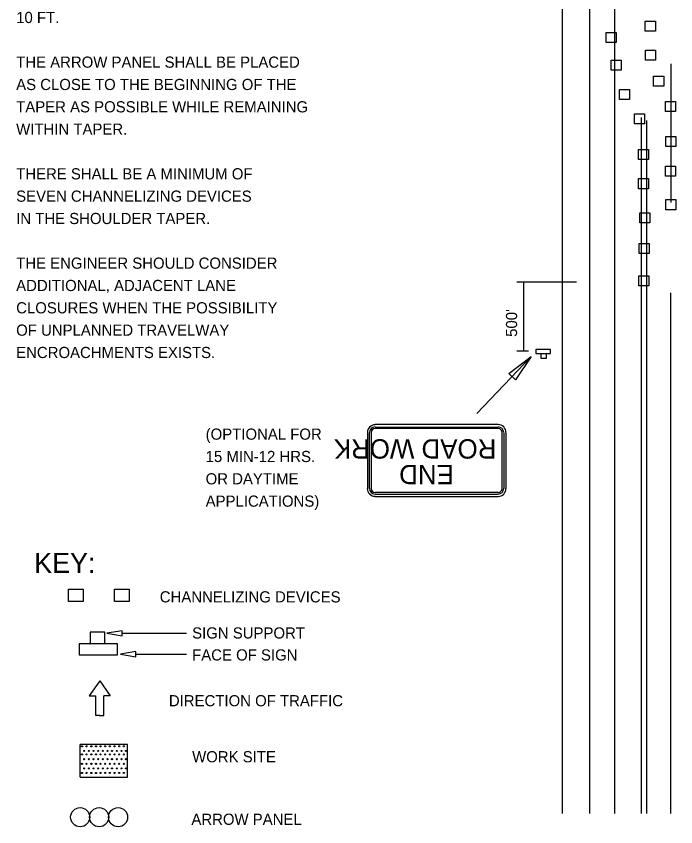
# Model space of a CAD drawing. Extents: x 15312.2 to 15319.5, y 15309 to 15319.2.
# Drawn here: x 15312.376 to 15315.922, y 15310.623 to 15314.978 of the extents above; entities that cross this region are included whole.
import ezdxf

# ---------------------------------------------------------------- set-up
doc = ezdxf.new("R2010")
doc.units = 0
for name, color, linetype in [('DETL-DIMS', 7, 'Continuous'), ('DETL-LINE', 7, 'Continuous'), ('DETL-NOTE', 7, 'Continuous'), ('DETL-TITL', 7, 'Continuous'), ('USER-BORD', 7, 'Continuous')]:
    doc.layers.add(name, color=color, linetype=linetype)

# ---------------------------------------------------------------- blocks, each defined once
blk = doc.blocks.new('CD1')
at = {"layer": 'USER-BORD'}
blk.add_lwpolyline([(0, 0.031), (0.031, 0.031), (0.031, 0), (0, 0)], close=True, dxfattribs=at)
blk = doc.blocks.new('SIGN13')
at = {"layer": 'USER-BORD'}
for points in [[(-0.013, 0.018), (0.011, 0.019), (0.011, 0.037), (-0.013, 0.037)], [(-0.031, 0.018), (-0.031, 0), (0.032, 0), (0.032, 0.018)]]:
    blk.add_lwpolyline(points, close=True, dxfattribs=at)
blk = doc.blocks.new('PANEL0')
at = {"layer": 'USER-BORD'}
for centre in [(0.0309, -0.0012), (0.0928, -0.0012), (0.1546, -0.0012)]:
    blk.add_circle(centre, 0.0312, dxfattribs=at)
blk = doc.blocks.new('DIR2')
at = {"layer": 'USER-BORD'}
for p, q in [((0, 0.001), (-0.034, -0.048)), ((0, 0.001), (0.034, -0.048)), ((-0.034, -0.048), (-0.013, -0.048)), ((-0.013, -0.113), (-0.013, -0.048)), ((0.034, -0.048), (0.013, -0.048)), ((0.013, -0.113), (0.013, -0.048)), ((-0.001, -0.113), (-0.013, -0.113)), ((-0.001, -0.113), (0.001, -0.113)), ((0.001, -0.113), (0.013, -0.113))]:
    blk.add_line(p, q, dxfattribs=at)

msp = doc.modelspace()

# ---------------------------------------------------------------- linework, layer by layer
at = {"layer": 'DETL-DIMS'}
for p, q in [((15315.389, 15313.549), (15315.067, 15313.549)), ((15315.105, 15313.178), (15315.105, 15313.549)), ((15315.131, 15313.178), (15315.067, 15313.178)), ((15315.145, 15313.149), (15314.853, 15312.844)), ((15312.946, 15311.662), (15313.291, 15311.662)), ((15313.02, 15311.55), (15313.291, 15311.55))]:
    msp.add_line(p, q, dxfattribs=at)
for points in [[(15315.06, 15313.024), (15315.024, 15313.058), (15315.145, 15313.149)], [(15312.946, 15311.648), (15312.946, 15311.676), (15312.863, 15311.662)], [(15313.02, 15311.536), (15313.02, 15311.564), (15312.937, 15311.55)]]:
    msp.add_lwpolyline(points, close=True, dxfattribs=at)
at = {"layer": 'DETL-LINE'}
for p, q in [((15315.312, 15318.785), (15315.312, 15310.694)), ((15315.458, 15318.785), (15315.458, 15310.694)), ((15315.594, 15310.694), (15315.594, 15315.696)), ((15315.895, 15314.722), (15315.895, 15313.976)), ((15315.735, 15314.434), (15315.735, 15310.694)), ((15315.765, 15314.418), (15315.765, 15310.694)), ((15315.895, 15310.694), (15315.895, 15313.492)), ((15314.967, 15312.784), (15314.306, 15312.784)), ((15314.306, 15312.77), (15314.967, 15312.77)), ((15314.264, 15312.74), (15314.264, 15312.44)), ((15314.276, 15312.44), (15314.276, 15312.74)), ((15314.285, 15312.74), (15314.285, 15312.44)), ((15314.967, 15312.762), (15314.306, 15312.762)), ((15314.9668, 15312.7625), (15314.9666, 15312.7619)), ((15314.989, 15312.44), (15314.989, 15312.74)), ((15314.997, 15312.74), (15314.997, 15312.44)), ((15315.01, 15312.44), (15315.01, 15312.74)), ((15314.967, 15312.418), (15314.306, 15312.418)), ((15314.306, 15312.41), (15314.306, 15312.41)), ((15314.306, 15312.41), (15314.967, 15312.41)), ((15314.306, 15312.398), (15314.967, 15312.398)), ((15312.974, 15311.064), (15312.72, 15311.064)), ((15312.974, 15311.064), (15312.72, 15311.064)), ((15312.974, 15311.064), (15312.72, 15311.064)), ((15312.974, 15311.064), (15312.72, 15311.064)), ((15312.7205, 15310.89), (15312.7205, 15311.064)), ((15312.7205, 15310.89), (15312.7205, 15311.064)), ((15312.729, 15311.055), (15312.729, 15311.055)), ((15312.73, 15311.055), (15312.73, 15311.055)), ((15312.742, 15311.03), (15312.742, 15311.03)), ((15312.742, 15311.03), (15312.742, 15311.03)), ((15312.755, 15311.055), (15312.755, 15311.055)), ((15312.755, 15311.055), (15312.755, 15311.055)), ((15312.767, 15311.03), (15312.767, 15311.03)), ((15312.767, 15311.03), (15312.767, 15311.03)), ((15312.779, 15311.055), (15312.779, 15311.055)), ((15312.78, 15311.055), (15312.78, 15311.055)), ((15312.792, 15311.03), (15312.792, 15311.03)), ((15312.792, 15311.03), (15312.792, 15311.03)), ((15312.804, 15311.055), (15312.804, 15311.055)), ((15312.805, 15311.055), (15312.805, 15311.055)), ((15312.817, 15311.03), (15312.817, 15311.03)), ((15312.817, 15311.03), (15312.817, 15311.03)), ((15312.829, 15311.055), (15312.829, 15311.055)), ((15312.83, 15311.055), (15312.83, 15311.055)), ((15312.842, 15311.03), (15312.842, 15311.03)), ((15312.842, 15311.03), (15312.842, 15311.03)), ((15312.855, 15311.055), (15312.855, 15311.055)), ((15312.855, 15311.055), (15312.855, 15311.055)), ((15312.867, 15311.03), (15312.867, 15311.03)), ((15312.867, 15311.03), (15312.867, 15311.03)), ((15312.879, 15311.055), (15312.879, 15311.055)), ((15312.879, 15311.055), (15312.879, 15311.055)), ((15312.891, 15311.03), (15312.891, 15311.03)), ((15312.891, 15311.03), (15312.891, 15311.03)), ((15312.904, 15311.055), (15312.904, 15311.055)), ((15312.905, 15311.055), (15312.905, 15311.055)), ((15312.917, 15311.03), (15312.917, 15311.03)), ((15312.917, 15311.03), (15312.917, 15311.03)), ((15312.929, 15311.055), (15312.929, 15311.055)), ((15312.93, 15311.055), (15312.93, 15311.055)), ((15312.942, 15311.03), (15312.942, 15311.03)), ((15312.942, 15311.03), (15312.942, 15311.03)), ((15312.955, 15311.055), (15312.955, 15311.055)), ((15312.955, 15311.055), (15312.955, 15311.055)), ((15312.967, 15311.03), (15312.967, 15311.03)), ((15312.967, 15311.03), (15312.967, 15311.03)), ((15312.974, 15310.89), (15312.974, 15311.064)), ((15312.974, 15310.89), (15312.974, 15311.064)), ((15312.974, 15310.89), (15312.974, 15311.064)), ((15312.974, 15310.89), (15312.974, 15311.064)), ((15312.729, 15311.011), (15312.729, 15311.011)), ((15312.73, 15311.011), (15312.73, 15311.011)), ((15312.742, 15310.986), (15312.742, 15310.986)), ((15312.755, 15311.011), (15312.755, 15311.011)), ((15312.755, 15311.011), (15312.755, 15311.011)), ((15312.767, 15310.986), (15312.767, 15310.986)), ((15312.779, 15311.011), (15312.779, 15311.011)), ((15312.78, 15311.011), (15312.78, 15311.011)), ((15312.792, 15310.986), (15312.792, 15310.986)), ((15312.804, 15311.011), (15312.804, 15311.011)), ((15312.805, 15311.011), (15312.805, 15311.011)), ((15312.817, 15310.986), (15312.817, 15310.986)), ((15312.829, 15311.011), (15312.829, 15311.011)), ((15312.83, 15311.011), (15312.83, 15311.011)), ((15312.842, 15310.986), (15312.842, 15310.986)), ((15312.855, 15311.011), (15312.855, 15311.011)), ((15312.855, 15311.011), (15312.855, 15311.011)), ((15312.867, 15310.986), (15312.867, 15310.986)), ((15312.879, 15311.011), (15312.879, 15311.011)), ((15312.879, 15311.011), (15312.879, 15311.011)), ((15312.891, 15310.986), (15312.891, 15310.986)), ((15312.904, 15311.011), (15312.904, 15311.011)), ((15312.905, 15311.011), (15312.905, 15311.011)), ((15312.917, 15310.986), (15312.917, 15310.986)), ((15312.929, 15311.011), (15312.929, 15311.011)), ((15312.93, 15311.011), (15312.93, 15311.011)), ((15312.942, 15310.986), (15312.942, 15310.986)), ((15312.955, 15311.011), (15312.955, 15311.011)), ((15312.955, 15311.011), (15312.955, 15311.011)), ((15312.967, 15310.986), (15312.967, 15310.986)), ((15312.729, 15310.961), (15312.729, 15310.961)), ((15312.73, 15310.961), (15312.73, 15310.961)), ((15312.755, 15310.961), (15312.755, 15310.961)), ((15312.755, 15310.961), (15312.755, 15310.961)), ((15312.779, 15310.961), (15312.779, 15310.961)), ((15312.78, 15310.961), (15312.78, 15310.961)), ((15312.804, 15310.961), (15312.804, 15310.961)), ((15312.805, 15310.961), (15312.805, 15310.961)), ((15312.829, 15310.961), (15312.829, 15310.961)), ((15312.83, 15310.961), (15312.83, 15310.961)), ((15312.855, 15310.961), (15312.855, 15310.961)), ((15312.855, 15310.961), (15312.855, 15310.961)), ((15312.879, 15310.961), (15312.879, 15310.961)), ((15312.879, 15310.961), (15312.879, 15310.961)), ((15312.904, 15310.961), (15312.904, 15310.961)), ((15312.905, 15310.961), (15312.905, 15310.961)), ((15312.929, 15310.961), (15312.929, 15310.961)), ((15312.93, 15310.961), (15312.93, 15310.961)), ((15312.955, 15310.961), (15312.955, 15310.961)), ((15312.955, 15310.961), (15312.955, 15310.961)), ((15312.729, 15310.912), (15312.729, 15310.912)), ((15312.73, 15310.912), (15312.73, 15310.912)), ((15312.742, 15310.936), (15312.742, 15310.936)), ((15312.742, 15310.936), (15312.742, 15310.936)), ((15312.755, 15310.912), (15312.755, 15310.912)), ((15312.755, 15310.912), (15312.755, 15310.912)), ((15312.767, 15310.936), (15312.767, 15310.936)), ((15312.767, 15310.936), (15312.767, 15310.936)), ((15312.779, 15310.912), (15312.779, 15310.912)), ((15312.78, 15310.912), (15312.78, 15310.912)), ((15312.792, 15310.936), (15312.792, 15310.936)), ((15312.792, 15310.936), (15312.792, 15310.936)), ((15312.804, 15310.912), (15312.804, 15310.912)), ((15312.805, 15310.912), (15312.805, 15310.912)), ((15312.817, 15310.936), (15312.817, 15310.936)), ((15312.817, 15310.936), (15312.817, 15310.936)), ((15312.829, 15310.912), (15312.829, 15310.912)), ((15312.83, 15310.912), (15312.83, 15310.912)), ((15312.842, 15310.936), (15312.842, 15310.936)), ((15312.842, 15310.936), (15312.842, 15310.936)), ((15312.855, 15310.912), (15312.855, 15310.912)), ((15312.855, 15310.912), (15312.855, 15310.912)), ((15312.867, 15310.936), (15312.867, 15310.936)), ((15312.867, 15310.936), (15312.867, 15310.936)), ((15312.879, 15310.912), (15312.879, 15310.912)), ((15312.879, 15310.912), (15312.879, 15310.912)), ((15312.891, 15310.936), (15312.891, 15310.936)), ((15312.891, 15310.936), (15312.891, 15310.936)), ((15312.904, 15310.912), (15312.904, 15310.912)), ((15312.905, 15310.912), (15312.905, 15310.912)), ((15312.917, 15310.936), (15312.917, 15310.936)), ((15312.917, 15310.936), (15312.917, 15310.936)), ((15312.929, 15310.912), (15312.929, 15310.912)), ((15312.93, 15310.912), (15312.93, 15310.912)), ((15312.942, 15310.936), (15312.942, 15310.936)), ((15312.942, 15310.936), (15312.942, 15310.936)), ((15312.955, 15310.912), (15312.955, 15310.912)), ((15312.955, 15310.912), (15312.955, 15310.912)), ((15312.967, 15310.936), (15312.967, 15310.936)), ((15312.967, 15310.936), (15312.967, 15310.936)), ((15312.7205, 15310.89), (15312.9744, 15310.89))]:
    msp.add_line(p, q, dxfattribs=at)
for points in [[(15315.594, 15314.774), (15315.594, 15314.804)], [(15315.594, 15314.744), (15315.594, 15314.774)], [(15315.594, 15314.534), (15315.594, 15314.564)], [(15315.895, 15314.572), (15315.895, 15314.472)], [(15315.594, 15314.504), (15315.594, 15314.534)], [(15315.594, 15314.294), (15315.594, 15314.324)], [(15315.594, 15314.264), (15315.594, 15314.294)], [(15315.895, 15314.172), (15315.895, 15314.072)], [(15315.594, 15314.054), (15315.594, 15314.084)], [(15315.594, 15314.024), (15315.594, 15314.054)], [(15315.594, 15313.814), (15315.594, 15313.844)], [(15315.594, 15313.784), (15315.594, 15313.814)], [(15315.594, 15313.574), (15315.594, 15313.604)], [(15315.594, 15313.544), (15315.594, 15313.574)], [(15315.594, 15313.334), (15315.594, 15313.364)], [(15315.895, 15313.334), (15315.895, 15313.364)], [(15315.594, 15313.304), (15315.594, 15313.334)], [(15315.895, 15313.304), (15315.895, 15313.334)], [(15315.594, 15313.094), (15315.594, 15313.124)], [(15315.895, 15313.094), (15315.895, 15313.124)], [(15315.594, 15313.064), (15315.594, 15313.094)], [(15315.895, 15313.064), (15315.895, 15313.094)], [(15315.594, 15312.854), (15315.594, 15312.884)], [(15315.895, 15312.854), (15315.895, 15312.884)], [(15315.594, 15312.824), (15315.594, 15312.854)], [(15315.895, 15312.824), (15315.895, 15312.854)], [(15315.594, 15312.614), (15315.594, 15312.644)], [(15315.895, 15312.614), (15315.895, 15312.644)], [(15315.594, 15312.584), (15315.594, 15312.614)], [(15315.895, 15312.584), (15315.895, 15312.614)], [(15315.594, 15312.374), (15315.594, 15312.404)], [(15315.895, 15312.374), (15315.895, 15312.404)], [(15315.594, 15312.344), (15315.594, 15312.374)], [(15315.895, 15312.344), (15315.895, 15312.374)], [(15315.594, 15312.134), (15315.594, 15312.164)], [(15315.895, 15312.134), (15315.895, 15312.164)], [(15315.594, 15312.104), (15315.594, 15312.134)], [(15315.895, 15312.104), (15315.895, 15312.134)], [(15315.594, 15311.894), (15315.594, 15311.924)], [(15315.895, 15311.894), (15315.895, 15311.924)], [(15315.594, 15311.864), (15315.594, 15311.894)], [(15315.895, 15311.864), (15315.895, 15311.894)], [(15315.594, 15311.654), (15315.594, 15311.684)], [(15315.895, 15311.654), (15315.895, 15311.684)], [(15315.594, 15311.624), (15315.594, 15311.654)], [(15315.895, 15311.624), (15315.895, 15311.654)], [(15315.594, 15311.414), (15315.594, 15311.444)], [(15315.895, 15311.414), (15315.895, 15311.444)], [(15315.594, 15311.384), (15315.594, 15311.414)], [(15315.895, 15311.384), (15315.895, 15311.414)], [(15315.594, 15311.174), (15315.594, 15311.204)], [(15315.895, 15311.174), (15315.895, 15311.204)], [(15315.594, 15311.144), (15315.594, 15311.174)], [(15315.895, 15311.144), (15315.895, 15311.174)], [(15315.594, 15310.934), (15315.594, 15310.964)], [(15315.895, 15310.934), (15315.895, 15310.964)], [(15315.594, 15310.904), (15315.594, 15310.934)], [(15315.895, 15310.904), (15315.895, 15310.934)], [(15315.594, 15310.694), (15315.594, 15310.724)], [(15315.895, 15310.694), (15315.895, 15310.724)]]:
    msp.add_lwpolyline(points, dxfattribs=at)
for points in [[(15312.658, 15311.833), (15312.658, 15311.9), (15312.737, 15311.9), (15312.737, 15311.833)], [(15312.904, 15311.833), (15312.904, 15311.9), (15312.983, 15311.9), (15312.983, 15311.833)]]:
    msp.add_lwpolyline(points, close=True, dxfattribs=at)
for centre in [(15312.7298, 15311.055), (15312.7418, 15311.0302), (15312.7546, 15311.055), (15312.7666, 15311.0302), (15312.7802, 15311.055), (15312.7922, 15311.0302), (15312.805, 15311.055), (15312.817, 15311.0302), (15312.8298, 15311.055), (15312.8418, 15311.0302), (15312.8546, 15311.055), (15312.8666, 15311.0302), (15312.8794, 15311.055), (15312.8914, 15311.0302), (15312.905, 15311.055), (15312.917, 15311.0302), (15312.9298, 15311.055), (15312.9418, 15311.0302), (15312.9546, 15311.055), (15312.9666, 15311.0302), (15312.7298, 15311.0113), (15312.7418, 15310.9857), (15312.7546, 15311.0113), (15312.7666, 15310.9857), (15312.7802, 15311.0113), (15312.7922, 15310.9857), (15312.805, 15311.0113), (15312.817, 15310.9857), (15312.8298, 15311.0113), (15312.8418, 15310.9857), (15312.8546, 15311.0113), (15312.8666, 15310.9857), (15312.8794, 15311.0113), (15312.8914, 15310.9857), (15312.905, 15311.0113), (15312.917, 15310.9857), (15312.9298, 15311.0113), (15312.9418, 15310.9857), (15312.9546, 15311.0113), (15312.9666, 15310.9857), (15312.7298, 15310.9609), (15312.7418, 15310.9361), (15312.7546, 15310.9609), (15312.7666, 15310.9361), (15312.7802, 15310.9609), (15312.7922, 15310.9361), (15312.805, 15310.9609), (15312.817, 15310.9361), (15312.8298, 15310.9609), (15312.8418, 15310.9361), (15312.8546, 15310.9609), (15312.8666, 15310.9361), (15312.8794, 15310.9609), (15312.8914, 15310.9361), (15312.905, 15310.9609), (15312.917, 15310.9361), (15312.9298, 15310.9609), (15312.9418, 15310.9361), (15312.9546, 15310.9609), (15312.9666, 15310.9361), (15312.7298, 15310.9117), (15312.7546, 15310.9117), (15312.7802, 15310.9117), (15312.805, 15310.9117), (15312.8298, 15310.9117), (15312.8546, 15310.9117), (15312.8794, 15310.9117), (15312.905, 15310.9117), (15312.9298, 15310.9117), (15312.9546, 15310.9117)]:
    msp.add_circle(centre, 0.00291, dxfattribs=at)
for centre, radius, start, end in [((15314.3056, 15312.7409), 0.0415, 90, 180), ((15314.3056, 15312.7409), 0.0301, 90, 180), ((15314.9668, 15312.7409), 0.0424, 0, 90), ((15314.9668, 15312.7409), 0.0301, 0, 90), ((15314.3056, 15312.7409), 0.0216, 90, 180), ((15314.9668, 15312.7409), 0.0216, 0, 90), ((15314.3056, 15312.4404), 0.0421, 180, 270), ((15314.3056, 15312.4404), 0.0301, 180, 270), ((15314.3056, 15312.4404), 0.0216, 180, 270), ((15314.9668, 15312.4404), 0.0424, 270, 0), ((15314.9668, 15312.4404), 0.0301, 270, 0), ((15314.9668, 15312.4404), 0.0216, 270, 0)]:
    msp.add_arc(centre, radius, start, end, dxfattribs=at)

# ---------------------------------------------------------------- block references
for name, p, xscale, yscale in [('CD1', (15315.758, 15314.897), 1.743723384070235, 1.743723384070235), ('CD1', (15315.548, 15314.836), 1.743723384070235, 1.743723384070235), ('CD1', (15315.759, 15314.742), 1.743723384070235, 1.743723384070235), ('CD1', (15315.574, 15314.687), 1.743723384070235, 1.743723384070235), ('CD1', (15315.803, 15314.602), 1.743723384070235, 1.743723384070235), ('CD1', (15315.62, 15314.53), 1.743723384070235, 1.743723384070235), ('CD1', (15315.866, 15314.465), 1.743723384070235, 1.743723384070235), ('CD1', (15315.7, 15314.399), 1.743723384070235, 1.743723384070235), ('CD1', (15315.868, 15314.277), 1.743723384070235, 1.743723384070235), ('CD1', (15315.722, 15314.208), 1.743723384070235, 1.743723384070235), ('CD1', (15315.866, 15314.118), 1.743723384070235, 1.743723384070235), ('CD1', (15315.722, 15314.051), 1.743723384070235, 1.743723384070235), ('CD1', (15315.868, 15313.938), 1.743723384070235, 1.743723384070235), ('CD1', (15315.728, 15313.868), 1.743723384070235, 1.743723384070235), ('CD1', (15315.725, 15313.702), 1.743723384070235, 1.743723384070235), ('CD1', (15315.723, 15313.529), 1.743723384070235, 1.743723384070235), ('SIGN13', (15312.816, 15311.547), 3.297838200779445, 3.297838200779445), ('DIR2', (15312.825, 15311.406), 1.6489191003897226, 1.6489191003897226), ('PANEL0', (15312.669, 15310.676), 1.6489191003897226, 1.6489191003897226)]:
    msp.add_blockref(name, p, dxfattribs=dict(at, xscale=xscale, yscale=yscale))
at = {"layer": 'DETL-LINE', "xscale": 1.236689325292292, "yscale": 1.236689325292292, "rotation": 180}
msp.add_blockref('SIGN13', (15315.21, 15313.187), dxfattribs=at)

# ---------------------------------------------------------------- texts
at = {"layer": 'DETL-LINE'}
for s, p in [('ROAD WORK', (15314.9574, 15312.705)), ('END', (15314.729, 15312.567))]:
    msp.add_text(s, height=0.1041, rotation=180, dxfattribs=at).set_placement(p)
at = {"layer": 'DETL-NOTE'}
for s, p in [('10 FT.', (15312.376, 15314.941)), ('THE ARROW PANEL SHALL BE PLACED', (15312.376, 15314.701)), ('AS CLOSE TO THE BEGINNING OF THE ', (15312.376, 15314.581)), ('TAPER AS POSSIBLE WHILE REMAINING', (15312.376, 15314.461)), ('WITHIN TAPER.', (15312.376, 15314.341)), ('THERE SHALL BE A MINIMUM OF ', (15312.376, 15314.101)), ('SEVEN CHANNELIZING DEVICES ', (15312.376, 15313.981)), ('IN THE SHOULDER TAPER.', (15312.376, 15313.861)), ('THE ENGINEER SHOULD CONSIDER', (15312.376, 15313.621)), ('ADDITIONAL, ADJACENT LANE', (15312.376, 15313.501)), ('CLOSURES WHEN THE POSSIBILITY', (15312.376, 15313.381)), ('OF UNPLANNED TRAVELWAY', (15312.376, 15313.261)), ('ENCROACHMENTS EXISTS.', (15312.376, 15313.141)), ('(OPTIONAL FOR', (15313.3946, 15312.7023)), ('15 MIN-12 HRS. ', (15313.3946, 15312.5823)), ('OR DAYTIME', (15313.3946, 15312.4623)), ('APPLICATIONS)', (15313.3946, 15312.3423)), ('CHANNELIZING DEVICES', (15313.148, 15311.828)), ('SIGN SUPPORT', (15313.322, 15311.634)), ('FACE OF SIGN', (15313.322, 15311.516)), ('DIRECTION OF TRAFFIC', (15313.197, 15311.27)), ('WORK SITE', (15313.322, 15310.969)), ('ARROW PANEL', (15313.318, 15310.633))]:
    msp.add_text(s, height=0.06, dxfattribs=at).set_placement(p)
msp.add_text("500'", height=0.06, rotation=90, dxfattribs=at).set_placement((15315.069, 15313.255))
at = {"layer": 'DETL-TITL'}
msp.add_text('KEY:', height=0.108, dxfattribs=at).set_placement((15312.473, 15311.986))

doc.saveas('drawing.dxf')
